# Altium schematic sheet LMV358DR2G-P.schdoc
size 127 x 101 mm
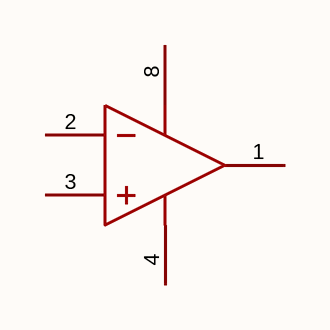
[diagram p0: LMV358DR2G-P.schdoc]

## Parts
U?  lmv358dr2g-p  [SOP-8_L5.0-W4.0-P1.27-LS6.0-BL]  (value not drawn)  (part A of 2)

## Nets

Not connected (* = marked no-connect by the designer): U? 1(OUTA) 2(INA-) 3(INA+) 4(VSS) 8(VDD)

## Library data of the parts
U? = lmv358dr2g-p: 放大器数:2;轨到轨:轨到轨输入,轨到轨输出;增益带宽积(GBW):1MHz;输入失调电压(Vos):5mV;压摆率(SR):600V/ms;输入偏置电流(Ib):10pA;; Manufacturer: TECH PUBLIC(台舟); AddInBom: yes; ModelId: a3315c1c78f949e6bb82c6eaca1c53c7; ModelName: SOP-8_L5.0-W4.0-H1.8-LS6.2-P1.27; ModelTransform: 244.094,196.85,0,90,0,0,0,0,0; Number of Channels: 2; Maximum Power Supply Range (Vdd-Vss): 7V; Gain Bandwidth Product: 1MHz; Vos - Input Offset Voltage: 5mV; Input Offset Voltage Drift(Vos TC): 2uV/℃; Ib - Input Bias Current: 10pA; Input Voltage Noise Density: 20nV/√Hz@10kHz; Common Mode Rejection Ratio(CMRR): 80dB; Quiescent Current: 40uA; Output Current: 20mA; Single supply: 2.5V~5.5V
